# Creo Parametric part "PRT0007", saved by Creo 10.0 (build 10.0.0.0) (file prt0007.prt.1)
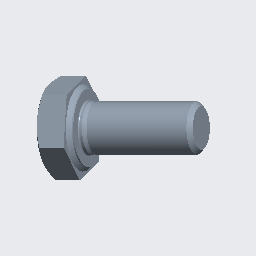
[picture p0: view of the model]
Units: millimeter Newton Second (mmNs); MM, TONNE, SECS

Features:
  1. coordinate system "SCHRAUBEN"
  2. imported feature "Import-ke ID 4"

Surfaces: 14 cone, 11 plane, 6 cylinder, 2 torus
